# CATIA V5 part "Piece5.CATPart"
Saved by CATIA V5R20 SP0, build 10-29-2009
Part number: Piece5
Bounding box of the stored display mesh (mm): x -2 to 0, y -5.641 to 47.412, z -5.647 to 31.503
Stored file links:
  D:\Dropbox\IAO_2012\IAO_2012_815_gcordenod\gcordenod\Piece5.CATPart
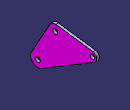
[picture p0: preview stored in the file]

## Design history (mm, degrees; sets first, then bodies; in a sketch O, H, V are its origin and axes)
Body1 (main body)
  Point1 "E": stored without definition
  Point2 "G": stored without definition
  Point3 "A": stored without definition
  Point4 "E": stored without definition
  Point5 "G": stored without definition
  Point6 "A": stored without definition
  Sketch1 on yz-plane, origin (0, 0, 0), H (0, 1, 0), V (0, 0, 1)
    point P1 (-4.9358, 2.7477)
    line L1 (-4.9358, 2.7477) -> (9.6526, 28.9529)
    arc A1 centre (13.9912, 26.5376) radius 4.9657 from (9.6526, 28.9529) to (14.6527, 31.459) cw
    line L2 (14.6527, 31.459) -> (44.3513, 27.4676)
    arc A2 centre (43.881, 23.9679) radius 3.5312 from (44.3513, 27.4676) to (45.7035, 20.9433) cw
    line L3 (45.7035, 20.9433) -> (2.9155, -4.8386)
    arc A3 centre (0, 0) radius 5.6491 from (2.9155, -4.8386) to (-4.9358, 2.7477) cw
    point P10 (-4.9358, 2.7477)
    reference projected point E1 (13.9912, 26.5376) from Point1
    reference projected point E2 (43.881, 23.9679) from Point2
    reference projected point E3 (0, 0) from Point3
    circle A4 centre (13.9912, 26.5376) radius 2
    reference projected point E4 (13.9912, 26.5376) from Point4
    circle A5 centre (0, 0) radius 2
    circle A6 centre (43.881, 23.9679) radius 1.8692
    reference projected point E5 (43.881, 23.9679) from Point5
    reference projected point E6 (0, 0) from Point6
    radius A1 = 4.9657
    radius A4 = 2
    radius A6 = 1.8692
    radius A5 = 2
    tangency: A1 L1, A2 L2, L3 A2, A3 L3, A3 L1, L2 A1
    coincidence: P10 L1, P10 P1
    concentricity: A1 E1, A2 E2, A3 E3, A4 E4, A6 E5, E6 A5
  Pad1: profile Sketch1, direction (-1, 0, 0), length 2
